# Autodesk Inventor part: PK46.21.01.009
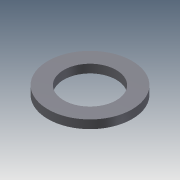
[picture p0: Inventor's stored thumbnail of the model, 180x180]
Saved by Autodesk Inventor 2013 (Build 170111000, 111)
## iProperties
Created: 2005-04
Part Number: PK46.21.01.009
Material: Steel, Mild
Document SubType Name: Modeling
Designer: salex
Manufacturer: Standard
Standards Organization: Custom
Density: 7.86 g/cm^3
Author: salex
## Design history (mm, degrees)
sketch "Эскиз1"
  geometry: C1 r 62.5 at (0, 0); C2 r 100 at (0, 0)
  constraints: 2 centre point, 1 coincident, 1 other
  dimensions: "d0" = 200 diameter of C2; "d1" = 125 diameter of C1
extrude "Выдавливание1" new body sketch "Эскиз1" distance "d2" = 20; taper "d3" = 0 deg
body "Solid1"
